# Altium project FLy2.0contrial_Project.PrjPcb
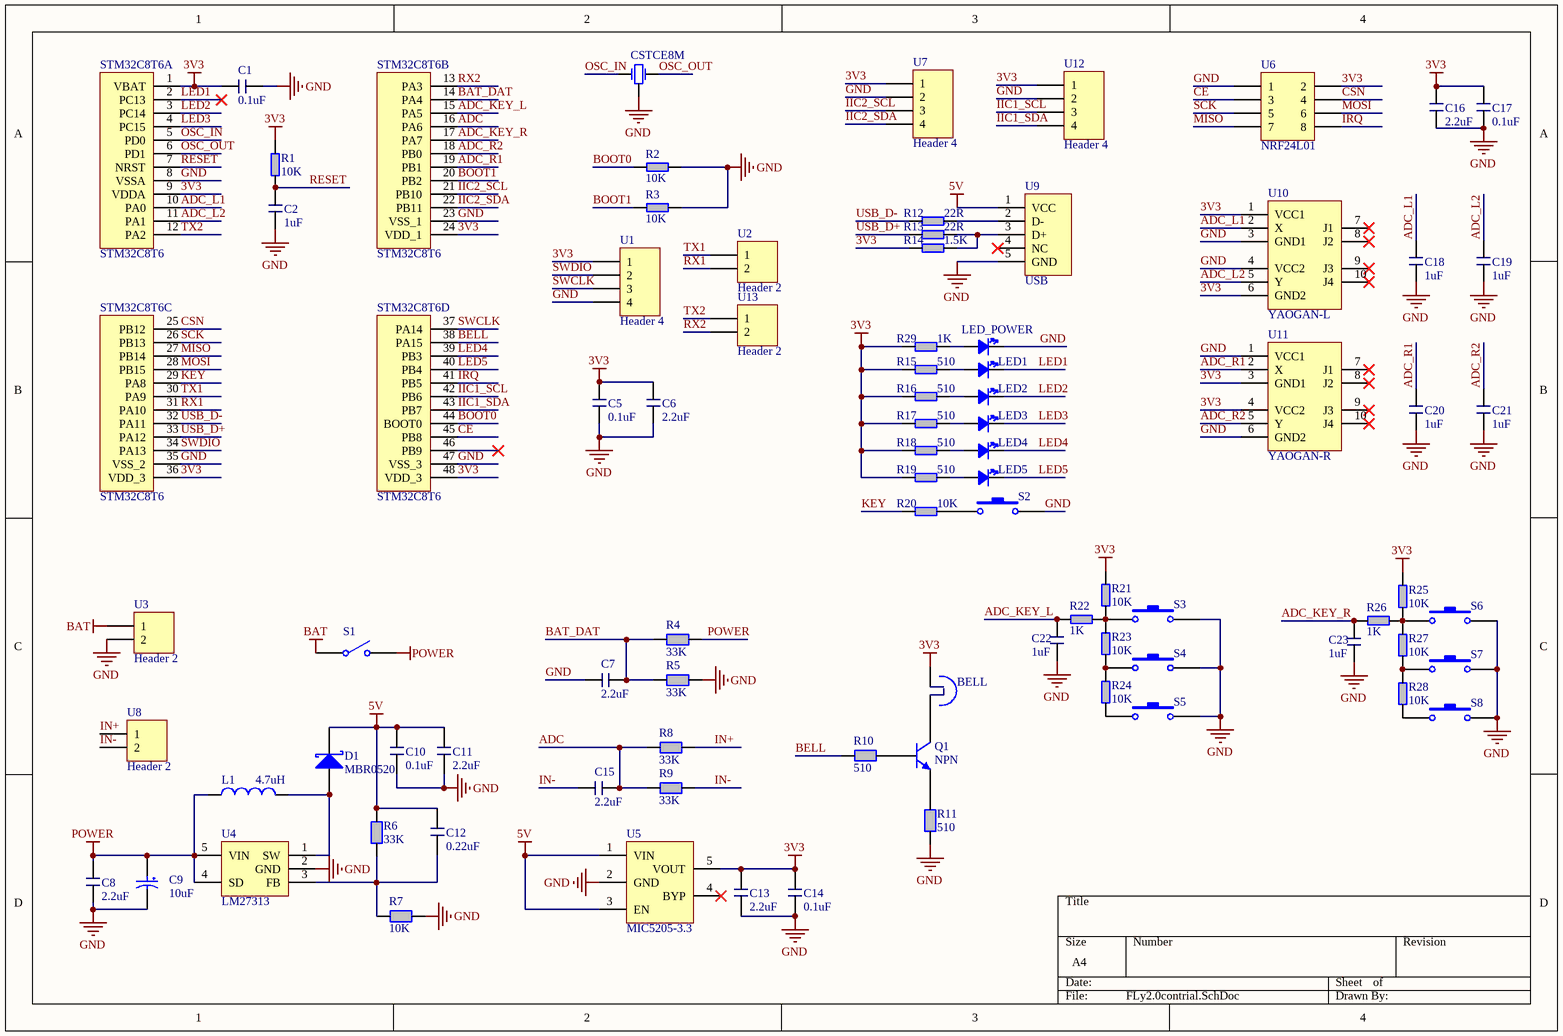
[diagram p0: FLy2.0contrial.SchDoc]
1 sheet, 83 parts. Net scope: global (net labels, ports and power ports of the same name join across sheets).
Board file: FLy2.0contrial.PcbDoc

## Sheet FLy2.0contrial.SchDoc
size A4

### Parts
BELL  BELL  [BELL]  (value not drawn)
C1  0.1uF  [0603]
C2  1uF  [0603]
C5  0.1uF  [0603]
C6  2.2uF  [0603]
C7  2.2uF  [0603]
C8  2.2uF  [0603]
C9  10uF  [CAP-A]
C10  0.1uF  [0603]
C11  2.2uF  [0603]
C12  0.22uF  [0603]
C13  2.2uF  [0603]
C14  0.1uF  [0603]
C15  2.2uF  [0603]
C16  2.2uF  [0603]
C17  0.1uF  [0603]
C18  1uF  [0603]
C19  1uF  [0603]
C20  1uF  [0603]
C21  1uF  [0603]
C22  1uF  [0603]
C23  1uF  [0603]
CSTCE8M  CSTCE8M  [CSTCE8M00G55-R0]  (value not drawn)
D1  MBR0520  [SOD_123]
L1  value 4.7uH  [L_4.7*4.7*1.8]  (hidden comment: Inductor)
LED1  LED  [0603]  (value not drawn)
LED2  LED  [0603]  (value not drawn)
LED3  LED  [0603]  (value not drawn)
LED4  LED  [0603]  (value not drawn)
LED5  LED  [0603]  (value not drawn)
LED_POWER  LED  [0603]  (value not drawn)
Q1  NPN  [TO-226-AA]
R1  10K  [0603]
R2  10K  [0603]
R3  10K  [0603]
R4  33K  [0603]
R5  33K  [0603]
R6  33K  [0603]
R7  10K  [0603]
R8  33K  [0603]
R9  33K  [0603]
R10  510  [0603]
R11  510  [0603]
R12  22R  [0805_1]
R13  22R  [0805_1]
R14  1.5K  [0805_1]
R15  510  [0603]
R16  510  [0603]
R17  510  [0603]
R18  510  [0603]
R19  510  [0603]
R20  10K  [0603]
R21  10K  [0603]
R22  1K  [0603]
R23  10K  [0603]
R24  10K  [0603]
R25  10K  [0603]
R26  1K  [0603]
R27  10K  [0603]
R28  10K  [0603]
R29  1K  [0805_1]
S1  SW-SPST  [SWITCH]  (value not drawn)
S2  SW-PB  [KEY]  (value not drawn)
S3  SW-PB  [KEY]  (value not drawn)
S4  SW-PB  [KEY]  (value not drawn)
S5  SW-PB  [KEY]  (value not drawn)
S6  SW-PB  [KEY]  (value not drawn)
S7  SW-PB  [KEY]  (value not drawn)
S8  SW-PB  [KEY]  (value not drawn)
STM32C8T6  STM32C8T6  [LQFP_48]  (parts A,B,C,D of 4)
U1  Header 4  [HDR1X4]
U2  Header 2  [HDR1X2]
U3  Header 2  [HDR1X2]
U4  LM27313  [SOT23-5]
U5  MIC5205-3.3  [SOT23-5]
U6  NRF24L01  [HDR2X4]
U7  Header 4  [OLED]
U8  Header 2  [HDR1X2]
U9  USB  [Micro USB]
U10  YAOGAN-L  [yaogan-r]
U11  YAOGAN-R  [yaogan-r]
U12  Header 4  [HDR1X4]
U13  Header 2  [HDR1X2]

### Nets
3V3: BELL.2 C1.1 C5.1 C6.1 C13.1 C14.1 C16.2 C17.2 R1.2 R14.1 R15.1 R16.1 R17.1 R18.1 R19.1 R21.2 R25.1 R29.1 STM32C8T6.1(VBAT) STM32C8T6.9(VDDA) STM32C8T6.24(VDD_1) STM32C8T6.36(VDD_3) STM32C8T6.48(VDD_3) U1.1 U5.5(VOUT) U6.2 U7.1 U10.1(VCC1) U10.6(GND2) U11.3(GND1) U11.4(VCC2) U12.1
5V: C10.1 C11.1 C12.1 D1.2(K) R6.1 U5.1(VIN) U5.3(EN) U9.1(VCC)
BAT: S1.1(COMMON) U3.1
GND: C1.2 C2.1 C5.2 C6.2 C7.1 C8.2 C9.2(M) C10.2 C11.2 C13.2 C14.2 C16.1 C17.1 C18.1 C19.1 C20.1 C21.1 C22.1 C23.1 CSTCE8M.2(GND) LED_POWER.2 R2.1 R3.1 R5.2 R7.2 R11.1 S2.2 S3.2 S4.2 S5.2 S6.2 S7.2 S8.2 STM32C8T6.8(VSSA) STM32C8T6.23(VSS_1) STM32C8T6.35(VSS_2) STM32C8T6.47(VSS_3) U1.4 U3.2 U4.2(GND) U5.2(GND) U6.1 U7.2 U9.5(GND) U10.3(GND1) U10.4(VCC2) U11.1(VCC1) U11.6(GND2) U12.2
POWER: C8.1 C9.1(P) L1.1 R4.2 S1.2(NO) U4.4(SD) U4.5(VIN)
ADC: C15.2 R8.1 R9.1 STM32C8T6.16(PA6)
ADC_KEY_L: C22.2 R22.2 STM32C8T6.15(PA5)
ADC_KEY_R: C23.2 R26.1 STM32C8T6.17(PA7)
ADC_L1: C18.2 STM32C8T6.10(PA0) U10.2(X)
ADC_L2: C19.2 STM32C8T6.11(PA1) U10.5(Y)
ADC_R1: C20.2 STM32C8T6.19(PB1) U11.2(X)
ADC_R2: C21.2 STM32C8T6.18(PB0) U11.5(Y)
BAT_DAT: C7.2 R4.1 R5.1 STM32C8T6.14(PA4)
BELL: R10.1 STM32C8T6.38(PA15)
BOOT0: R2.2 STM32C8T6.44(BOOT0)
BOOT1: R3.2 STM32C8T6.20(PB2)
CE: STM32C8T6.45(PB8) U6.3
CSN: STM32C8T6.25(PB12) U6.4
IIC1_SCL: STM32C8T6.42(PB6) U12.3
IIC1_SDA: STM32C8T6.43(PB7) U12.4
IIC2_SCL: STM32C8T6.21(PB10) U7.3
IIC2_SDA: STM32C8T6.22(PB11) U7.4
IN+: R8.2 U8.1
IN-: C15.1 R9.2 U8.2
IRQ: STM32C8T6.41(PB5) U6.8
KEY: R20.1 STM32C8T6.29(PA8)
LED1: LED1.2 STM32C8T6.2(PC13)
LED2: LED2.2 STM32C8T6.3(PC14)
LED3: LED3.2 STM32C8T6.4(PC15)
LED4: LED4.2 STM32C8T6.39(PB3)
LED5: LED5.2 STM32C8T6.40(PB4)
MISO: STM32C8T6.27(PB14) U6.7
MOSI: STM32C8T6.28(PB15) U6.6
OSC_IN: CSTCE8M.1(OSC1) STM32C8T6.5(PD0)
OSC_OUT: CSTCE8M.3(OSC2) STM32C8T6.6(PD1)
RESET: C2.2 R1.1 STM32C8T6.7(NRST)
RX1: STM32C8T6.31(PA10) U2.2
RX2: STM32C8T6.13(PA3) U13.2
SCK: STM32C8T6.26(PB13) U6.5
SWCLK: STM32C8T6.37(PA14) U1.3
SWDIO: STM32C8T6.34(PA13) U1.2
TX1: STM32C8T6.30(PA9) U2.1
TX2: STM32C8T6.12(PA2) U13.1
USB_D+: R13.1 STM32C8T6.33(PA12)
USB_D-: R12.1 STM32C8T6.32(PA11)
NetBELL_1: BELL.1 Q1.1(C)
NetC12_2: C12.2 R6.2 R7.1 U4.3(FB)
NetD1_1: D1.1(A) L1.2 U4.1(SW)
NetLED1_1: LED1.1 R15.2
NetLED2_1: LED2.1 R16.2
NetLED3_1: LED3.1 R17.2
NetLED4_1: LED4.1 R18.2
NetLED5_1: LED5.1 R19.2
NetLED_POWER_1: LED_POWER.1 R29.2
NetQ1_2: Q1.2(B) R10.2
NetQ1_3: Q1.3(E) R11.2
NetR12_2: R12.2 U9.2(D-)
NetR13_2: R13.2 R14.2 U9.3(D+)
NetR20_2: R20.2 S2.1
NetR21_1: R21.1 R22.1 R23.1 S3.1
NetR23_2: R23.2 R24.1 S4.1
NetR24_2: R24.2 S5.1
NetR25_2: R25.2 R26.2 R27.2 S6.1
NetR27_1: R27.1 R28.2 S7.1
NetR28_1: R28.1 S8.1

Not connected (* = marked no-connect by the designer): STM32C8T6 46(PB9)*; U5 4(BYP)*; U9 4(NC)*; U10 7(J1)* 8(J2)* 9(J3)* 10(J4)*; U11 7(J1)* 8(J2)* 9(J3)* 10(J4)*

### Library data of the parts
C1 C2 C5-C8 C15-C23 = C-0603
C9 = CAP-T
C10-C14 = C-0805
D1 = Diode 11DQ03: Schottky Rectifier
L1 = Inductor: Code_IEC: 1005
Q1 = NPN: NPN Bipolar Transistor
R1-R3 R12-R29 = R-0603
R4-R11 = R0805
S1 = SW-SPST: Single-Pole, Single-Throw Switch
S2-S8 = SW-PB: Switch
STM32C8T6 = STM32F103C8T6
U1 U7 U12 = Header 4: Header, 4-Pin
U2 U3 U8 U13 = Header 2: Header, 2-Pin
U6 = Header 4X2: Header, 4-Pin, Dual row
U10 = YAOGAN-R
